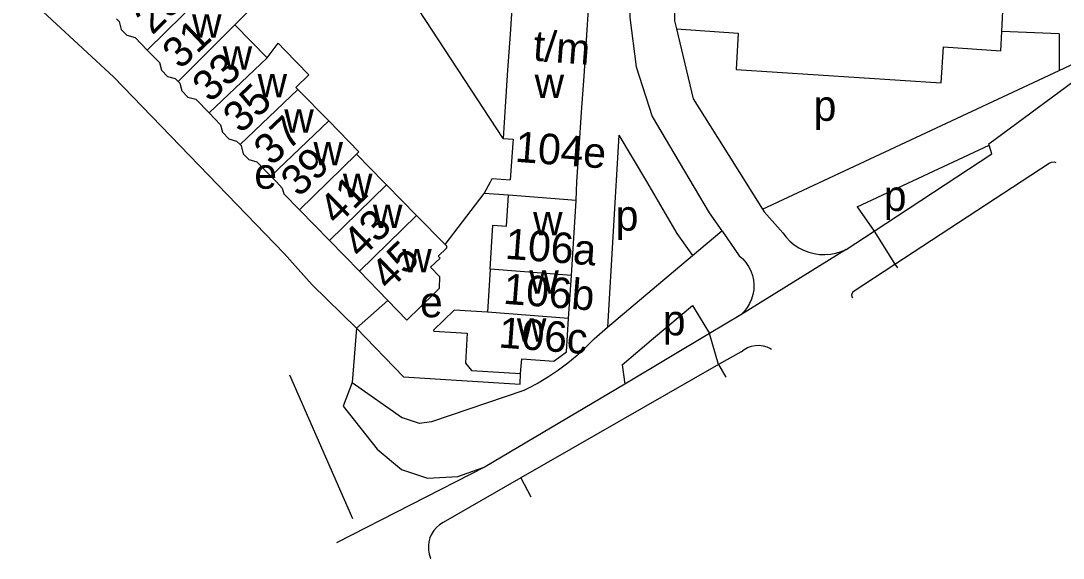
# Model space of a CAD drawing. Extents: x 159261 to 160849, y 382514 to 384534.
# Drawn here: x 160487.8 to 160624.3, y 382700.7 to 382771.1 of the extents above; entities that cross this region are included whole.
import ezdxf

# ---------------------------------------------------------------- set-up
doc = ezdxf.new("R2010")
doc.units = 0
for name, color, linetype in [('BLT_Basislijn', 7, 'Continuous'), ('BLT_Bebouwing', 7, 'Continuous'), ('BLT_Centroide', 7, 'Continuous'), ('BLT_Huisnummer', 7, 'Continuous'), ('BLT_Huisnummer_ tussenligend', 7, 'Continuous'), ('BLT_Huisnummer_reeks', 7, 'Continuous'), ('BLT_Onderverdeling_panden', 7, 'Continuous'), ('BLT_Vlakafsluiter', 7, 'Continuous')]:
    doc.layers.add(name, color=color, linetype=linetype)

msp = doc.modelspace()

# ---------------------------------------------------------------- linework, layer by layer
at = {"layer": 'BLT_Basislijn'}
for p, q in [((160616.3, 382769.71), (160616.83, 382780.84)), ((160573.69, 382770.06), (160581.78, 382769.51)), ((160616.18, 382767.18), (160616.3, 382769.71)), ((160623.81, 382769.43), (160616.3, 382769.71)), ((160623.81, 382769.43), (160623.81, 382764.61)), ((160608.65, 382767.69), (160616.18, 382767.18)), ((160623.81, 382764.61), (160628.4, 382766.75)), ((160584.95, 382746.44), (160623.81, 382764.61)), ((160566.16, 382756.12), (160564.67, 382730.95)), ((160597.37, 382746.73), (160614.64, 382754.8)), ((160602.31, 382739.22), (160622.49, 382752.45)), ((160543.4, 382741.8), (160548.52, 382748.49)), ((160584.95, 382746.44), (160585.17, 382746.09)), ((160585.17, 382746.09), (160587.63, 382743.33)), ((160597.37, 382746.73), (160599.58, 382743.55)), ((160575.81, 382740.36), (160579.65, 382743.59)), ((160579.65, 382743.59), (160579.71, 382743.5)), ((160579.71, 382743.5), (160581.9, 382740.32)), ((160595.92, 382741.16), (160599.58, 382743.55)), ((160567.46, 382733.33), (160575.81, 382740.36)), ((160596.84, 382735.63), (160602.31, 382739.22)), ((160602.31, 382739.22), (160602.65, 382738.74)), ((160531.81, 382730.82), (160526.01, 382736.53)), ((160531.81, 382730.82), (160535.91, 382734.46)), ((160570.68, 382729.51), (160575.78, 382733.8)), ((160575.78, 382733.8), (160578.04, 382730.13)), ((160564.67, 382730.95), (160567.46, 382733.33)), ((160582.12, 382732.57), (160578.04, 382730.13)), ((160531.81, 382730.82), (160531.24, 382723.72)), ((160562.92, 382729.45), (160564.67, 382730.95)), ((160578.04, 382730.13), (160566.94, 382723.51)), ((160566.59, 382726.05), (160570.68, 382729.51)), ((160582.16, 382727.75), (160579.2, 382726.06)), ((160579.2, 382726.06), (160553.31, 382711.22)), ((160566.59, 382726.05), (160566.94, 382723.51)), ((160579.2, 382726.06), (160580.16, 382724.42)), ((160523.01, 382724.74), (160531.25, 382705.89)), ((160531.24, 382723.72), (160530.03, 382720.6)), ((160531.24, 382723.72), (160537.82, 382719.1)), ((160566.94, 382723.51), (160548.65, 382712.68)), ((160553.73, 382722.68), (160541.6, 382718.56)), ((160553.31, 382711.22), (160543.13, 382705.38)), ((160553.31, 382711.22), (160554.62, 382708.75))]:
    msp.add_line(p, q, dxfattribs=at)
for points in [[(160563.96, 382801.92), (160569.11, 382801.6), (160567.92, 382787.11), (160567.59, 382779.01), (160567.59, 382771.56), (160568.4, 382765.08), (160570.51, 382758.59), (160574.07, 382752.6), (160577.96, 382745.95), (160579.65, 382743.59)], [(160551, 382755.68), (160539.11, 382773.86), (160535.06, 382777.54)], [(160573.44, 382776.1), (160573.44, 382771.11), (160573.69, 382770.06)], [(160526.01, 382736.53), (160522.33, 382740.64), (160500, 382763.72), (160487.84, 382775.04)], [(160573.69, 382770.06), (160575.87, 382760.9), (160580.57, 382753.45), (160584.95, 382746.44)], [(160581.78, 382769.51), (160581.53, 382764.72), (160608.36, 382762.97), (160608.65, 382767.69)], [(160614.64, 382754.8), (160614.59, 382754.99), (160628.46, 382765.2), (160629.26, 382767.16)], [(160566.16, 382756.12), (160569.76, 382750.06), (160573.76, 382743.23), (160575.81, 382740.36)], [(160599.58, 382743.55), (160614.98, 382753.68), (160614.64, 382754.8)], [(160622.49, 382752.45), (160622.81, 382752.58), (160623.14, 382752.62), (160623.38, 382752.55)], [(160587.63, 382743.33), (160588.06, 382742.76), (160588.56, 382742.24), (160589.11, 382741.78), (160589.71, 382741.38), (160590.35, 382741.05), (160591.02, 382740.79), (160591.71, 382740.61), (160592.43, 382740.51), (160593.14, 382740.49), (160593.86, 382740.54), (160594.57, 382740.68), (160595.25, 382740.89), (160595.92, 382741.16)], [(160581.9, 382740.32), (160582.37, 382739.91), (160582.79, 382739.43), (160583.14, 382738.91), (160583.43, 382738.35), (160583.64, 382737.76), (160583.78, 382737.14), (160583.83, 382736.51), (160583.81, 382735.88), (160583.71, 382735.26), (160583.53, 382734.65), (160583.27, 382734.08), (160582.95, 382733.54), (160582.55, 382733.04), (160582.12, 382732.57)], [(160596.84, 382735.63), (160596.6, 382735.27), (160596.68, 382734.93), (160596.77, 382734.82)], [(160531.81, 382730.82), (160537.93, 382724.48), (160553.22, 382723.51), (160553.29, 382724.89)], [(160562.92, 382729.45), (160561.83, 382728.33), (160560.68, 382727.27), (160559.48, 382726.27), (160558.23, 382725.33), (160556.94, 382724.46), (160555.6, 382723.65), (160554.22, 382722.92), (160553.73, 382722.68)], [(160582.16, 382727.75), (160582.57, 382728.06), (160583.02, 382728.31), (160583.51, 382728.48), (160584.02, 382728.58), (160584.53, 382728.6), (160585.04, 382728.53), (160585.54, 382728.39), (160586.01, 382728.18), (160586.14, 382728.09)], [(160530.03, 382720.6), (160534.49, 382714.98), (160537.68, 382712.31), (160541.1, 382711.19), (160545.08, 382711.41), (160547.63, 382712.34), (160548.65, 382712.68)], [(160541.6, 382718.56), (160540.03, 382718.36), (160537.82, 382719.1)], [(160543.13, 382705.38), (160542.67, 382705.09), (160542.26, 382704.73), (160541.91, 382704.32), (160541.63, 382703.86), (160541.41, 382703.36), (160541.27, 382702.83), (160541.21, 382702.3), (160541.23, 382701.75), (160541.33, 382701.22), (160541.5, 382700.71), (160541.51, 382700.7)]]:
    msp.add_lwpolyline(points, dxfattribs=at)
at = {"layer": 'BLT_Bebouwing'}
for p, q in [((160552.22, 382774.07), (160551.91, 382769.35)), ((160561.91, 382768.59), (160562.23, 382773.31)), ((160515.85, 382770.6), (160520.09, 382766.27)), ((160551.91, 382769.35), (160551.59, 382764.63)), ((160561.6, 382763.87), (160561.91, 382768.59)), ((160551.59, 382764.63), (160551.28, 382759.91)), ((160561.28, 382759.15), (160561.6, 382763.87)), ((160524.12, 382762.13), (160528.15, 382757.99)), ((160551.28, 382759.91), (160551, 382755.68)), ((160560.97, 382754.43), (160561.28, 382759.15)), ((160552.26, 382755.09), (160551.94, 382750.28)), ((160535.73, 382749.63), (160539.65, 382745.62)), ((160528.25, 382742.32), (160524.32, 382746.35)), ((160539.65, 382745.62), (160543.4, 382741.8)), ((160532.17, 382738.3), (160528.25, 382742.32)), ((160535.91, 382734.46), (160532.17, 382738.3)), ((160559.56, 382732.12), (160559.93, 382737.76)), ((160538.4, 382731.91), (160535.91, 382734.46)), ((160559.28, 382727.76), (160559.56, 382732.12))]:
    msp.add_line(p, q, dxfattribs=at)
for points in [[(160513.82, 382776.55), (160517.79, 382772.51), (160515.85, 382770.6)], [(160500.36, 382771.39), (160500.71, 382771.04), (160500.98, 382769.99), (160501.72, 382769.23), (160502.8, 382768.93), (160504.39, 382767.29)], [(160520.09, 382766.27), (160521.54, 382768.17), (160522.42, 382767.27), (160525.56, 382764.05), (160523.86, 382762.39), (160524.12, 382762.13)], [(160504.39, 382767.29), (160505.98, 382765.66), (160506.24, 382764.65), (160507.03, 382763.84), (160508.06, 382763.55), (160508.43, 382763.16)], [(160508.43, 382763.16), (160508.65, 382762.93), (160508.91, 382761.93), (160509.7, 382761.12), (160510.74, 382760.83), (160512.49, 382759.04)], [(160512.49, 382759.04), (160513.99, 382757.49), (160514.24, 382756.51), (160515.08, 382755.65), (160516.1, 382755.36), (160516.54, 382754.91)], [(160528.15, 382757.99), (160532.1, 382753.94), (160531.81, 382753.65)], [(160551, 382755.68), (160552.3, 382755.59), (160552.26, 382755.09)], [(160516.54, 382754.91), (160516.68, 382754.76), (160516.95, 382753.69), (160517.7, 382752.93), (160518.74, 382752.63), (160520.56, 382750.76)], [(160560.56, 382747.59), (160560.67, 382750), (160560.97, 382754.43)], [(160531.81, 382753.65), (160535.37, 382749.99), (160535.73, 382749.63)], [(160520.56, 382750.76), (160521.31, 382750), (160522.08, 382749.2), (160522.27, 382748.46), (160524.32, 382746.35)], [(160548.52, 382748.49), (160549.34, 382750), (160549.58, 382750.44), (160551.94, 382750.28)], [(160551.72, 382748.26), (160548.52, 382748.49)], [(160549.29, 382738.57), (160549.67, 382744.34), (160551.42, 382744.22), (160551.72, 382748.26)], [(160559.93, 382737.76), (160560.56, 382747.59)], [(160543.4, 382741.8), (160543.58, 382741.61), (160543.58, 382741.33), (160542.48, 382740.27), (160542.73, 382740.02), (160541.49, 382738.82)], [(160541.49, 382738.82), (160542.65, 382737.62), (160542.64, 382736.04), (160541.98, 382735.4), (160538.4, 382731.91)], [(160549.29, 382738.57), (160548.93, 382732.93)], [(160548.93, 382732.93), (160544.58, 382733.22), (160541.86, 382730.57), (160541.93, 382730.46), (160546.29, 382730.18), (160546.09, 382726.26), (160546.84, 382725.31), (160553.29, 382724.89)], [(160553.29, 382724.89), (160553.45, 382726.82), (160557.64, 382726.52), (160559.28, 382727.76)]]:
    msp.add_lwpolyline(points, dxfattribs=at)
at = {"layer": 'BLT_Onderverdeling_panden'}
for p, q in [((160504.39, 382767.29), (160513.82, 382776.55)), ((160508.43, 382763.16), (160515.85, 382770.6)), ((160512.49, 382759.04), (160520.09, 382766.27)), ((160516.54, 382754.91), (160524.12, 382762.13)), ((160520.56, 382750.76), (160528.15, 382757.99)), ((160524.32, 382746.35), (160531.81, 382753.65)), ((160528.25, 382742.32), (160535.73, 382749.63)), ((160560.56, 382747.59), (160551.72, 382748.26)), ((160532.17, 382738.3), (160539.65, 382745.62)), ((160559.93, 382737.76), (160549.29, 382738.57)), ((160559.56, 382732.12), (160548.93, 382732.93))]:
    msp.add_line(p, q, dxfattribs=at)
at = {"layer": 'BLT_Vlakafsluiter'}
for p, q in [((160599.58, 382743.55), (160602.31, 382739.22)), ((160595.92, 382741.16), (160582.12, 382732.57)), ((160579.2, 382726.06), (160578.04, 382730.13)), ((160548.65, 382712.68), (160529.19, 382702.71))]:
    msp.add_line(p, q, dxfattribs=at)

# ---------------------------------------------------------------- texts
at = {"layer": 'BLT_Centroide'}
for s, p in [('w', (160510.26, 382768.91)), ('w', (160514.27, 382764.72)), ('w', (160518.84, 382761.09)), ('w', (160555.12, 382761.01)), ('p', (160591.66, 382758.01)), ('w', (160522.34, 382756.44)), ('w', (160526.16, 382752.16)), ('e', (160518.41, 382749.11)), ('w', (160530.02, 382748)), ('p', (160600.85, 382746.2)), ('w', (160533.95, 382743.97)), ('w', (160554.92, 382743)), ('p', (160565.74, 382743.62)), ('w', (160537.78, 382738.16)), ('w', (160554.42, 382735.34)), ('e', (160540.11, 382732.27)), ('p', (160571.91, 382729.9)), ('w', (160552.8, 382729.06))]:
    msp.add_text(s, height=4, dxfattribs=at).set_placement(p)
at = {"layer": 'BLT_Huisnummer'}
for s, rotation, p in [('31', 43.5824, (160508.73, 382764.64)), ('35', 43.5839, (160516.66, 382756.23)), ('39', 44.2636, (160524.28, 382747.89)), ('106a', 355.6438, (160551.17, 382739.95)), ('45', 44.4086, (160536.04, 382735.62)), ('106b', 355.6438, (160550.93, 382734.05)), ('106c', 355.6438, (160550.32, 382728.32))]:
    msp.add_text(s, height=4, rotation=rotation, dxfattribs=at).set_placement(p)
at = {"layer": 'BLT_Huisnummer_ tussenligend'}
for s, rotation, p in [('29', 44.2647, (160505.05, 382769.17)), ('33', 43.5824, (160512.65, 382760.29)), ('37', 43.5839, (160520.69, 382751.98)), ('41', 44.2636, (160529.26, 382744.16)), ('43', 44.2636, (160532.37, 382739.8))]:
    msp.add_text(s, height=4, rotation=rotation, dxfattribs=at).set_placement(p)
at = {"layer": 'BLT_Huisnummer_reeks'}
for s, rotation, p in [('84-a-b', 312.3364, (160622.24, 382780.47)), ('t/m', 355.6438, (160554.84, 382765.91)), ('104e', 355.6392, (160552.47, 382752.66))]:
    msp.add_text(s, height=4, rotation=rotation, dxfattribs=at).set_placement(p)

doc.saveas('drawing.dxf')
